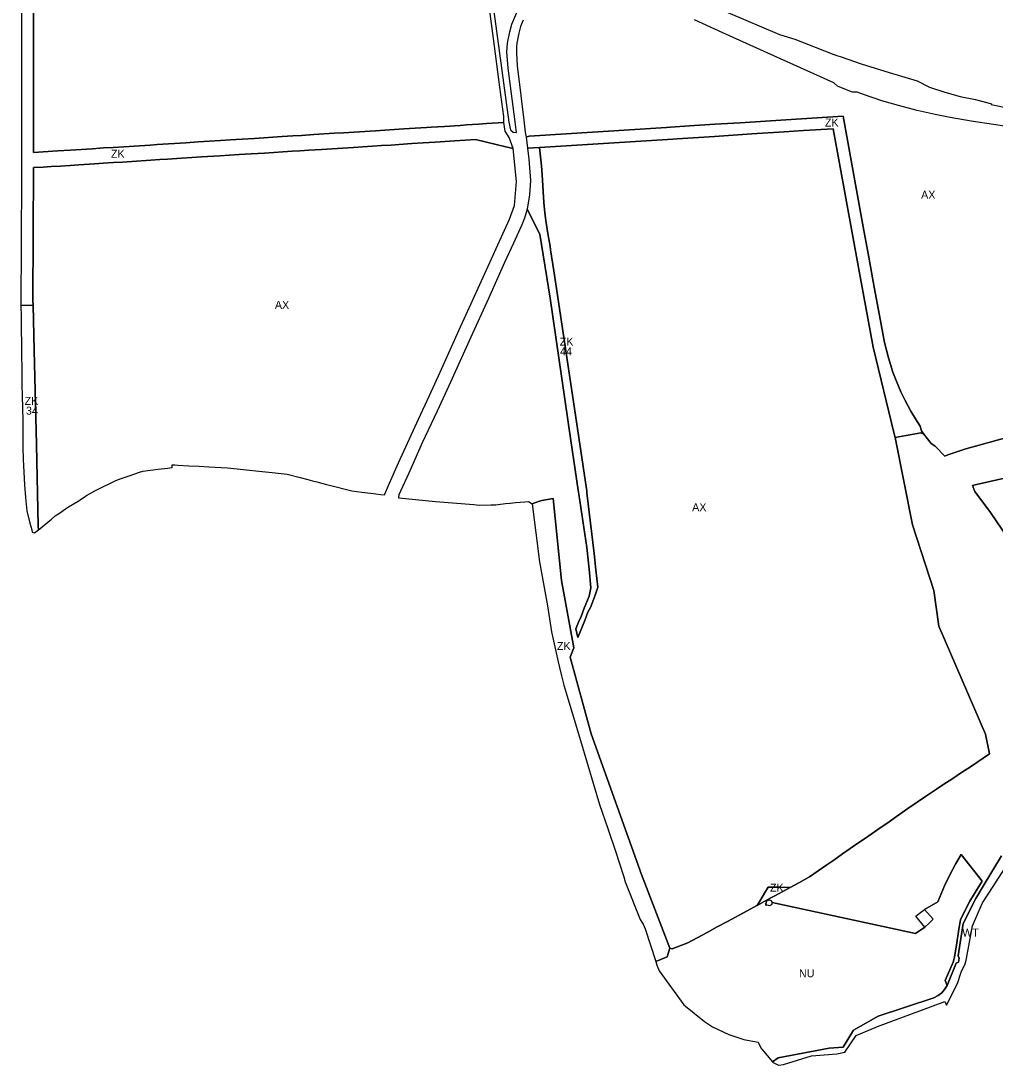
# Model space of a CAD drawing. Extents: x -521939 to -516426, y -1197857 to -1189551.
# Drawn here: x -520595 to -519377, y -1194163 to -1192859 of the extents above; entities that cross this region are included whole.
import ezdxf

# ---------------------------------------------------------------- set-up
doc = ezdxf.new("R2010")
doc.units = 0
for name, color, linetype in [('90640013', 7, 'Continuous'), ('90710013', 7, 'Continuous'), ('90710023', 7, 'Continuous'), ('90730013', 7, 'Continuous'), ('90760013', 7, 'Continuous'), ('ID_navrh', 7, 'Continuous')]:
    doc.layers.add(name, color=color, linetype=linetype)

msp = doc.modelspace()

# ---------------------------------------------------------------- linework, layer by layer
at = {"layer": '90640013'}
msp.add_lwpolyline([(-519369.32, -1193902.04), (-519392.44, -1193939.94), (-519401.67, -1193955.07), (-519417.38, -1193986.45), (-519423.71, -1194026.84), (-519422.25, -1194029.85), (-519423.14, -1194034.81), (-519426.12, -1194036.14), (-519437.56, -1194064.1), (-519440.57, -1194068.9), (-519444.16, -1194073.19), (-519448.49, -1194076.43), (-519453.99, -1194079.26), (-519523.58, -1194102.28), (-519554.3, -1194119.84), (-519567.25, -1194140.88), (-519584.65, -1194142.29), (-519648.63, -1194154.46), (-519655.75, -1194159.37), (-519655.45, -1194159.52), (-519647.94, -1194163.37), (-519641.85, -1194162.57), (-519606.91, -1194151.78), (-519575.26, -1194149.43), (-519565.1, -1194147.14), (-519550.87, -1194126.48), (-519524.59, -1194115.17), (-519440.38, -1194083.75), (-519438.01, -1194088.36), (-519424.43, -1194061.23), (-519420.05, -1194047.18), (-519414.79, -1194036.92), (-519413.61, -1194032.27), (-519413.11, -1194030.31), (-519405.75, -1193989.16), (-519399.04, -1193973.83), (-519393.3, -1193960.72), (-519380, -1193940.17), (-519361.83, -1193912.1)], dxfattribs=at)
at = {"layer": '90710013'}
for points in [[(-520593.65, -1192846.53), (-520593.65, -1192886.47), (-520593.65, -1192919.05), (-520593.65, -1192951.65), (-520593.65, -1193003.95), (-520593.65, -1193022.39), (-520593.65, -1193025.86), (-520593.83, -1193063.74), (-520594.11, -1193124.54), (-520594.19, -1193141.12), (-520594.27, -1193157.6), (-520594.44, -1193193.51), (-520594.51, -1193208.54), (-520594.54, -1193214.33), (-520579.39, -1193213.66), (-520579.51, -1193208.61), (-520578.73, -1193042.06), (-520566.88, -1193041.27), (-520556.71, -1193040.64), (-520545.11, -1193039.99), (-520533.1, -1193039.2), (-520522.29, -1193038.46), (-520502.67, -1193037.25), (-520491.62, -1193036.59), (-520478.81, -1193035.71), (-520467.56, -1193034.99), (-520455.8, -1193034.25), (-520432.23, -1193032.75), (-520420.8, -1193032.06), (-520411.37, -1193031.46), (-520393.95, -1193030.39), (-520380.96, -1193029.53), (-520368.83, -1193028.73), (-520345.83, -1193027.27), (-520322.05, -1193025.77), (-520306.84, -1193024.79), (-520290.21, -1193023.75), (-520255.59, -1193021.55), (-520245.93, -1193020.94), (-520240.07, -1193020.58), (-520234.93, -1193020.24), (-520219.13, -1193019.25), (-520178.86, -1193016.69), (-520167.73, -1193015.98), (-520155.48, -1193015.24), (-520143.99, -1193014.49), (-520132.24, -1193013.75), (-520106.15, -1193012.06), (-520091.82, -1193011.2), (-520077.11, -1193010.24), (-520052.32, -1193008.69), (-520026.61, -1193007.06), (-519988.7, -1193015.91), (-519979.35, -1193018.09), (-519984.44, -1193004.38), (-519989.51, -1192996.39), (-519991.05, -1192985.7), (-520012.89, -1192987.09), (-520022.91, -1192987.66), (-520037.92, -1192988.72), (-520045.66, -1192989.26), (-520065.26, -1192990.45), (-520082.11, -1192991.54), (-520087.74, -1192991.91), (-520116.16, -1192993.69), (-520151.57, -1192995.93), (-520178, -1192997.58), (-520191.65, -1192998.39), (-520203.14, -1192999.13), (-520228.56, -1193000.81), (-520243.85, -1193001.69), (-520254.89, -1193002.46), (-520268.06, -1193003.31), (-520302.87, -1193005.42), (-520317.98, -1193006.45), (-520333.21, -1193007.43), (-520345.29, -1193008.1), (-520358.83, -1193009.02), (-520373, -1193009.89), (-520388.44, -1193010.92), (-520424.27, -1193013.22), (-520433.04, -1193013.75), (-520479.44, -1193016.7), (-520491.25, -1193017.47), (-520505.08, -1193018.37), (-520533.01, -1193020.12), (-520548.56, -1193021.06), (-520578.65, -1193022.99), (-520578.65, -1192845.72)], [(-519961.59, -1193017.82), (-519946.52, -1193016.85), (-519780.28, -1193006.26), (-519774.46, -1193005.9), (-519728.13, -1193002.94), (-519693.03, -1193000.71), (-519681.4, -1192999.94), (-519640.92, -1192997.38), (-519616.64, -1192995.84), (-519579.74, -1192993.48), (-519548.08, -1193166.93), (-519529.92, -1193266.42), (-519503.38, -1193374.77), (-519502.33, -1193379.15), (-519470.46, -1193373.47), (-519466.38, -1193375.11), (-519469.48, -1193370.72), (-519471.11, -1193364.85), (-519476.92, -1193356.09), (-519482.58, -1193346.45), (-519490.34, -1193332.09), (-519495.18, -1193322.01), (-519501.24, -1193308), (-519505.08, -1193297.39), (-519510.86, -1193279.84), (-519515.74, -1193260.34), (-519522, -1193226.57), (-519528.39, -1193191.55), (-519535.25, -1193153.85), (-519542.14, -1193116.18), (-519550.99, -1193067.69), (-519567.38, -1192977.66), (-519638.79, -1192982.16), (-519695.85, -1192985.85), (-519727.53, -1192987.89), (-519759.2, -1192989.89), (-519777.13, -1192991.04), (-519783.15, -1192991.42), (-519787.9, -1192991.72), (-519959.5, -1193002.65), (-519963.23, -1193004.02), (-519961.59, -1193017.82)], [(-519783.96, -1194017.34), (-519819.1, -1193925.23), (-519882.21, -1193749.64), (-519908.38, -1193653.77), (-519903.71, -1193641.87), (-519919.19, -1193557.82), (-519929.74, -1193455.31), (-519943.76, -1193457.81), (-519947.7, -1193459.17), (-519955.63, -1193461.89), (-519946.78, -1193534.59), (-519936.7, -1193589.63), (-519931.56, -1193622.07), (-519923.3, -1193659.68), (-519921.57, -1193666.61), (-519919.01, -1193676.86), (-519916.08, -1193688.59), (-519895.34, -1193757.93), (-519871.53, -1193837.56), (-519861.11, -1193867.84), (-519850.99, -1193898.71), (-519847.64, -1193908.92), (-519841.31, -1193928.23), (-519839.55, -1193934.52), (-519820.78, -1193981.48), (-519818.64, -1193984.6), (-519816.99, -1193987.28), (-519814.49, -1193992.92), (-519801.37, -1194033.88), (-519786.98, -1194028.03), (-519783.96, -1194017.34)], [(-519674.87, -1193963.79), (-519665.13, -1193958.51), (-519661.44, -1193956.51), (-519657.74, -1193954.5), (-519652.7, -1193951.75), (-519633.36, -1193941.29), (-519647.22, -1193941.11), (-519661.09, -1193940.94), (-519665.71, -1193948.61), (-519670.34, -1193956.28), (-519674.87, -1193963.79)]]:
    msp.add_lwpolyline(points, dxfattribs=at)
at = {"layer": '90710023'}
for points in [[(-519962.06, -1193093.75), (-519946.35, -1193125.19), (-519933.38, -1193205.21), (-519907.35, -1193382.83), (-519898.22, -1193445.13), (-519897.8, -1193447.56), (-519897.38, -1193449.99), (-519887.36, -1193516.57), (-519884.47, -1193543.82), (-519882.69, -1193567.19), (-519884.76, -1193577.59), (-519890.7, -1193592.62), (-519894.55, -1193602.68), (-519897.73, -1193609.81), (-519901.37, -1193618.32), (-519898.76, -1193628.94), (-519889.94, -1193607.87), (-519886.16, -1193597.43), (-519883.14, -1193591.58), (-519880.89, -1193586.23), (-519877.16, -1193576.19), (-519873.92, -1193566.11), (-519876.28, -1193544.38), (-519878.23, -1193524.18), (-519887.53, -1193448.24), (-519887.69, -1193445.77), (-519887.86, -1193443.3), (-519901.66, -1193351.49), (-519928.77, -1193171.13), (-519932.83, -1193144.89), (-519933.44, -1193140.29), (-519936.08, -1193124.31), (-519938.56, -1193107.97), (-519940.04, -1193098.62), (-519941.21, -1193085.76), (-519943.25, -1193050.97), (-519944.11, -1193039.95), (-519945.63, -1193024.86), (-519946.52, -1193016.85), (-519961.59, -1193017.82), (-519959.95, -1193031.63), (-519957.98, -1193057.97), (-519959.22, -1193075.94), (-519962.06, -1193093.75)], [(-520572.69, -1193494.62), (-520572.81, -1193489.53), (-520575.23, -1193388.1), (-520578.05, -1193270.09), (-520579.39, -1193213.66), (-520594.54, -1193214.33), (-520594.36, -1193228.5), (-520594.2, -1193241.7), (-520593.91, -1193264.71), (-520593.84, -1193270.47), (-520593.48, -1193299.21), (-520593.16, -1193312.67), (-520592.81, -1193327.52), (-520592.34, -1193342.18), (-520592.11, -1193358.68), (-520592.07, -1193374.76), (-520592.13, -1193390.79), (-520591.63, -1193406.88), (-520590.94, -1193422.65), (-520590.74, -1193422.65), (-520589.86, -1193438.24), (-520588.57, -1193454.26), (-520586.93, -1193470.68), (-520583.19, -1193486.29), (-520581, -1193494.61), (-520580.28, -1193497.37), (-520577.34, -1193498.47), (-520572.69, -1193494.62)]]:
    msp.add_lwpolyline(points, dxfattribs=at)
at = {"layer": '90730013'}
for points in [[(-519363, -1193379.33), (-519414.21, -1193393.4), (-519436.58, -1193400.77), (-519440.32, -1193402.59), (-519452.18, -1193390.07), (-519457.37, -1193386.9), (-519466.38, -1193375.11), (-519470.46, -1193373.47), (-519502.33, -1193379.15), (-519480.86, -1193488.16), (-519453.95, -1193570.4), (-519447.84, -1193614.85), (-519389.47, -1193750.04), (-519384.42, -1193774.3), (-519408.2, -1193790.66), (-519418.05, -1193797.11), (-519431.74, -1193806.08), (-519441.36, -1193812.44), (-519450.66, -1193818.5), (-519464.32, -1193827.57), (-519486.62, -1193842.93), (-519503.63, -1193854.82), (-519509.92, -1193859.26), (-519524.03, -1193869.16), (-519536.51, -1193877.89), (-519553.25, -1193889.05), (-519568.04, -1193899.4), (-519579.1, -1193907.2), (-519587.75, -1193913.3), (-519609.4, -1193928.24), (-519622.78, -1193935.57), (-519633.36, -1193941.29), (-519652.7, -1193951.75), (-519657.74, -1193954.5), (-519661.44, -1193956.51), (-519659.93, -1193956.89), (-519657.33, -1193957.77), (-519656.64, -1193959), (-519655.91, -1193960.31), (-519477.05, -1193998.98), (-519465.18, -1193990.9)], [(-519355.68, -1193513.49), (-519383.3, -1193472.91), (-519402.88, -1193446.79), (-519405.79, -1193439.04), (-519400.65, -1193437.87), (-519323.14, -1193420.3)], [(-519674.87, -1193963.79), (-519675.09, -1193963.91), (-519687.29, -1193970.52), (-519711.79, -1193983.75), (-519724.57, -1193990.65), (-519737.33, -1193997.55), (-519761.2, -1194010.43), (-519780.88, -1194018.05), (-519783.96, -1194017.34), (-519786.98, -1194028.03), (-519801.37, -1194033.88), (-519799.88, -1194038.54), (-519797.27, -1194045.4), (-519766.42, -1194087.98), (-519740.5, -1194108.83), (-519730.5, -1194115.53), (-519710.16, -1194125.22), (-519691.18, -1194131.21), (-519673.57, -1194134.61), (-519672.17, -1194137.42), (-519669.38, -1194143.02), (-519668.94, -1194143.55), (-519655.75, -1194159.37), (-519648.63, -1194154.46), (-519584.65, -1194142.29), (-519567.25, -1194140.88), (-519554.3, -1194119.84), (-519523.58, -1194102.28), (-519453.99, -1194079.26), (-519448.49, -1194076.43), (-519444.16, -1194073.19), (-519440.57, -1194068.9), (-519437.56, -1194064.1), (-519439.91, -1194057.85), (-519429.83, -1194034.63), (-519428.59, -1194030.27), (-519428.22, -1194027.94), (-519425.91, -1194013.45), (-519422.59, -1193993.31), (-519420.77, -1193981.9), (-519415.68, -1193971.51), (-519408.84, -1193958.58), (-519404.57, -1193950.95), (-519401.16, -1193945.56), (-519393.46, -1193933.48), (-519419.72, -1193900.08), (-519426.85, -1193912.47), (-519433.98, -1193925.44), (-519440.59, -1193939.19), (-519448.9, -1193959.21), (-519465.49, -1193968.92), (-519454.84, -1193980.91), (-519460.01, -1193985.91), (-519465.18, -1193990.9), (-519477.05, -1193998.98), (-519655.91, -1193960.31), (-519656.75, -1193962.97), (-519659.4, -1193964.35), (-519662.02, -1193963.62), (-519662.24, -1193963.25), (-519663.26, -1193963.82), (-519663.79, -1193962.87), (-519664.31, -1193961.92), (-519663.23, -1193961.31), (-519663.44, -1193960.89), (-519662.65, -1193958.29), (-519659.93, -1193956.89), (-519661.44, -1193956.51), (-519665.13, -1193958.51), (-519674.87, -1193963.79)], [(-519465.18, -1193990.9), (-519476.58, -1193977.08), (-519472.45, -1193974.05), (-519465.49, -1193968.92), (-519448.9, -1193959.21), (-519440.59, -1193939.19), (-519433.98, -1193925.44), (-519426.85, -1193912.47), (-519419.72, -1193900.08), (-519393.46, -1193933.48), (-519401.16, -1193945.56), (-519404.57, -1193950.95), (-519408.84, -1193958.58), (-519415.68, -1193971.51), (-519420.77, -1193981.9), (-519422.59, -1193993.31), (-519425.91, -1194013.45), (-519428.22, -1194027.94), (-519428.59, -1194030.27), (-519429.83, -1194034.63), (-519439.91, -1194057.85), (-519437.56, -1194064.1), (-519426.12, -1194036.14), (-519423.14, -1194034.81), (-519422.25, -1194029.85), (-519423.71, -1194026.84), (-519417.38, -1193986.45), (-519401.67, -1193955.07), (-519392.44, -1193939.94), (-519369.32, -1193902.04)]]:
    msp.add_lwpolyline(points, dxfattribs=at)
at = {"layer": '90760013'}
for points in [[(-520578.65, -1192845.72), (-520578.65, -1193022.99), (-520548.56, -1193021.06), (-520533.01, -1193020.12), (-520505.08, -1193018.37), (-520491.25, -1193017.47), (-520479.44, -1193016.7), (-520433.04, -1193013.75), (-520424.27, -1193013.22), (-520388.44, -1193010.92), (-520373, -1193009.89), (-520358.83, -1193009.02), (-520345.29, -1193008.1), (-520333.21, -1193007.43), (-520317.98, -1193006.45), (-520302.87, -1193005.42), (-520268.06, -1193003.31), (-520254.89, -1193002.46), (-520243.85, -1193001.69), (-520228.56, -1193000.81), (-520203.14, -1192999.13), (-520191.65, -1192998.39), (-520178, -1192997.58), (-520151.57, -1192995.93), (-520116.16, -1192993.69), (-520087.74, -1192991.91), (-520082.11, -1192991.54), (-520065.26, -1192990.45), (-520045.66, -1192989.26), (-520037.92, -1192988.72), (-520022.91, -1192987.66), (-520012.89, -1192987.09), (-519991.05, -1192985.7), (-519991.11, -1192978.26), (-519996.02, -1192941.34), (-520004.11, -1192880.48), (-520009.13, -1192843.07)], [(-520003.51, -1192847.12), (-519985.11, -1192985.35), (-519982.68, -1192994.68), (-519979.39, -1192997.86), (-519975.28, -1192998.31)], [(-519975.28, -1192998.31), (-519976.99, -1192984.86), (-519985.67, -1192917.82), (-519987.63, -1192897.15), (-519986.6, -1192886.41), (-519983.86, -1192872.26), (-519981.06, -1192862.78), (-519973.79, -1192845.48)], [(-519711.44, -1192848.38), (-519646.77, -1192875.82), (-519627.56, -1192881.34), (-519578.96, -1192900.47), (-519578.65, -1192900.59), (-519575.19, -1192901.81), (-519569.95, -1192903.63), (-519544.98, -1192912.28), (-519509.74, -1192923.15), (-519475.01, -1192933.77), (-519459.24, -1192941.4), (-519440.39, -1192947.55), (-519421.33, -1192953.08), (-519401.78, -1192957), (-519382, -1192962.28), (-519382.21, -1192963.28), (-519360.04, -1192967.68)], [(-519966.94, -1192857.93), (-519970.35, -1192865.66), (-519972.67, -1192873.95), (-519975.08, -1192886.33), (-519975.27, -1192891.17), (-519975.59, -1192898.9), (-519974.75, -1192915.01), (-519972.14, -1192935.43), (-519970.58, -1192948.05), (-519968.79, -1192962.75), (-519968.01, -1192968.78), (-519966.28, -1192982.61), (-519964.4, -1192997.62), (-519963.23, -1193004.02), (-519959.5, -1193002.65), (-519787.9, -1192991.72), (-519783.15, -1192991.42), (-519777.13, -1192991.04), (-519759.2, -1192989.89), (-519727.53, -1192987.89), (-519695.85, -1192985.85), (-519638.79, -1192982.16), (-519567.38, -1192977.66), (-519550.99, -1193067.69), (-519542.14, -1193116.18), (-519535.25, -1193153.85), (-519528.39, -1193191.55), (-519522, -1193226.57), (-519515.74, -1193260.34), (-519510.86, -1193279.84), (-519505.08, -1193297.39), (-519501.24, -1193308), (-519495.18, -1193322.01), (-519490.34, -1193332.09), (-519482.58, -1193346.45), (-519476.92, -1193356.09), (-519471.11, -1193364.85), (-519469.48, -1193370.72), (-519466.38, -1193375.11), (-519457.37, -1193386.9), (-519452.18, -1193390.07), (-519440.32, -1193402.59), (-519436.58, -1193400.77), (-519414.21, -1193393.4), (-519363, -1193379.33)], [(-519316.79, -1192997.86), (-519379.4, -1192988.21), (-519407.22, -1192983.93), (-519433.72, -1192979.51), (-519452.37, -1192975.76), (-519474.87, -1192970.68), (-519498.2, -1192964.55), (-519518.93, -1192958.37), (-519542.07, -1192950.61), (-519549.76, -1192947.78), (-519555.74, -1192947.57), (-519567.2, -1192943.06), (-519574.51, -1192940.18), (-519579.08, -1192936.23), (-519653.99, -1192902.46), (-519717.76, -1192873.41), (-519752.94, -1192857.37)], [(-519674.87, -1193963.79), (-519670.34, -1193956.28), (-519665.71, -1193948.61), (-519661.09, -1193940.94), (-519647.22, -1193941.11), (-519633.36, -1193941.29), (-519622.78, -1193935.57), (-519609.4, -1193928.24), (-519587.75, -1193913.3), (-519579.1, -1193907.2), (-519568.04, -1193899.4), (-519553.25, -1193889.05), (-519536.51, -1193877.89), (-519524.03, -1193869.16), (-519509.92, -1193859.26), (-519503.63, -1193854.82), (-519486.62, -1193842.93), (-519464.32, -1193827.57), (-519450.66, -1193818.5), (-519441.36, -1193812.44), (-519431.74, -1193806.08), (-519418.05, -1193797.11), (-519408.2, -1193790.66), (-519384.42, -1193774.3), (-519389.47, -1193750.04), (-519447.84, -1193614.85), (-519453.95, -1193570.4), (-519480.86, -1193488.16), (-519502.33, -1193379.15), (-519503.38, -1193374.77), (-519529.92, -1193266.42), (-519548.08, -1193166.93), (-519579.74, -1192993.48), (-519616.64, -1192995.84), (-519640.92, -1192997.38), (-519681.4, -1192999.94), (-519693.03, -1193000.71), (-519728.13, -1193002.94), (-519774.46, -1193005.9), (-519780.28, -1193006.26), (-519946.52, -1193016.85), (-519945.63, -1193024.86), (-519944.11, -1193039.95), (-519943.25, -1193050.97), (-519941.21, -1193085.76), (-519940.04, -1193098.62), (-519938.56, -1193107.97), (-519936.08, -1193124.31), (-519933.44, -1193140.29), (-519932.83, -1193144.89), (-519928.77, -1193171.13), (-519901.66, -1193351.49), (-519887.86, -1193443.3), (-519887.69, -1193445.77), (-519887.53, -1193448.24), (-519878.23, -1193524.18), (-519876.28, -1193544.38), (-519873.92, -1193566.11), (-519877.16, -1193576.19), (-519880.89, -1193586.23), (-519883.14, -1193591.58), (-519886.16, -1193597.43), (-519889.94, -1193607.87), (-519898.76, -1193628.94), (-519901.37, -1193618.32), (-519897.73, -1193609.81), (-519894.55, -1193602.68), (-519890.7, -1193592.62), (-519884.76, -1193577.59), (-519882.69, -1193567.19), (-519884.47, -1193543.82), (-519887.36, -1193516.57), (-519897.38, -1193449.99), (-519897.8, -1193447.56), (-519898.22, -1193445.13), (-519907.35, -1193382.83), (-519933.38, -1193205.21), (-519946.35, -1193125.19), (-519962.06, -1193093.75), (-519965.3, -1193105.27), (-519968.9, -1193113.5), (-519979.15, -1193136.45), (-519990.26, -1193160.72), (-520002.08, -1193186.73), (-520010.57, -1193205.51), (-520032.44, -1193253.64), (-520057.96, -1193310.06), (-520074.37, -1193346.48), (-520093.16, -1193385.99), (-520110.08, -1193423.75), (-520120.13, -1193446.45), (-520122.19, -1193450.64), (-520122.83, -1193454.58), (-520118.08, -1193455.09), (-520076.7, -1193459.13), (-520028.77, -1193463.02), (-520025.22, -1193463.32), (-520021.66, -1193463.62), (-520007.58, -1193463.4), (-520001.4, -1193463.3), (-519998.48, -1193462.95), (-519989.19, -1193461.84), (-519983.09, -1193461.11), (-519976.68, -1193460.34), (-519964.98, -1193459.47), (-519960.33, -1193459.13), (-519955.63, -1193461.89), (-519947.7, -1193459.17), (-519943.76, -1193457.81), (-519929.74, -1193455.31), (-519919.19, -1193557.82), (-519903.71, -1193641.87), (-519908.38, -1193653.77), (-519882.21, -1193749.64), (-519819.1, -1193925.23), (-519783.96, -1194017.34), (-519780.88, -1194018.05), (-519761.2, -1194010.43), (-519737.33, -1193997.55), (-519724.57, -1193990.65), (-519711.79, -1193983.75), (-519687.29, -1193970.52), (-519675.09, -1193963.91), (-519674.87, -1193963.79)], [(-519979.35, -1193018.09), (-519988.7, -1193015.91), (-520026.61, -1193007.06), (-520052.32, -1193008.69), (-520077.11, -1193010.24), (-520091.82, -1193011.2), (-520106.15, -1193012.06), (-520132.24, -1193013.75), (-520143.99, -1193014.49), (-520155.48, -1193015.24), (-520167.73, -1193015.98), (-520178.86, -1193016.69), (-520219.13, -1193019.25), (-520234.93, -1193020.24), (-520240.07, -1193020.58), (-520245.93, -1193020.94), (-520255.59, -1193021.55), (-520290.21, -1193023.75), (-520306.84, -1193024.79), (-520322.05, -1193025.77), (-520345.83, -1193027.27), (-520368.83, -1193028.73), (-520380.96, -1193029.53), (-520393.95, -1193030.39), (-520411.37, -1193031.46), (-520420.8, -1193032.06), (-520432.23, -1193032.75), (-520455.8, -1193034.25), (-520467.56, -1193034.99), (-520478.81, -1193035.71), (-520491.62, -1193036.59), (-520502.67, -1193037.25), (-520522.29, -1193038.46), (-520533.1, -1193039.2), (-520545.11, -1193039.99), (-520556.71, -1193040.64), (-520566.88, -1193041.27), (-520578.73, -1193042.06), (-520579.51, -1193208.61), (-520579.39, -1193213.66), (-520578.05, -1193270.09), (-520575.23, -1193388.1), (-520572.81, -1193489.53), (-520572.69, -1193494.62), (-520556.47, -1193481.19), (-520552.19, -1193477.64), (-520551.51, -1193477.08), (-520546.33, -1193473.58), (-520538.63, -1193468.36), (-520534.87, -1193466.02), (-520523.12, -1193458.7), (-520520.53, -1193457.08), (-520515.1, -1193453.26), (-520512.4, -1193451.62), (-520508.9, -1193449.5), (-520502.06, -1193445.99), (-520494.81, -1193442.28), (-520493.13, -1193441.44), (-520481.96, -1193435.8), (-520476.06, -1193432.83), (-520469.36, -1193430.53), (-520458.12, -1193426.67), (-520446.45, -1193422.65), (-520442, -1193421.12), (-520422.98, -1193418.9), (-520411.57, -1193417.55), (-520405.38, -1193416.83), (-520405.38, -1193413.23), (-520402.17, -1193413.42), (-520398.39, -1193413.64), (-520384.74, -1193414.44), (-520371.74, -1193415.2), (-520359.55, -1193415.91), (-520336.49, -1193417.25), (-520332.09, -1193417.51), (-520312.6, -1193419.64), (-520297.31, -1193421.3), (-520280.67, -1193423.11), (-520261.82, -1193425.17), (-520245.85, -1193429.27), (-520235.96, -1193431.81), (-520230.21, -1193433.29), (-520225.01, -1193434.63), (-520212.61, -1193437.82), (-520209.03, -1193438.74), (-520181.19, -1193445.89), (-520168.44, -1193447.43), (-520157.33, -1193448.78), (-520145.02, -1193450.27), (-520140.41, -1193450.83), (-520133.9, -1193436.21), (-520122.68, -1193410.82), (-520097.84, -1193356.45), (-520084.24, -1193326.9), (-520070.77, -1193297.42), (-520047.22, -1193245.62), (-520021.04, -1193188.07), (-519984.32, -1193106.32), (-519978.09, -1193089.18), (-519975.45, -1193059.33), (-519979.35, -1193018.09)], [(-519323.14, -1193420.3), (-519400.65, -1193437.87), (-519405.79, -1193439.04), (-519402.88, -1193446.79), (-519383.3, -1193472.91), (-519355.68, -1193513.49)]]:
    msp.add_lwpolyline(points, dxfattribs=at)

# ---------------------------------------------------------------- texts
at = {"layer": '90640013'}
msp.add_text('WT', height=10, rotation=0, dxfattribs=at).set_placement((-519418.48, -1194002.7))
at = {"layer": '90710013'}
for rotation, p in [(360, (-519590.1, -1192990.64)), (360, (-520482.02, -1193029.72)), (0, (-519924.87, -1193644.73)), (360, (-519658.73, -1193946.68))]:
    msp.add_text('ZK', height=10, rotation=rotation, dxfattribs=at).set_placement(p)
at = {"layer": '90710023'}
for rotation, p in [(360, (-519921.33, -1193264.44)), (0, (-520589.92, -1193338.47))]:
    msp.add_text('ZK', height=10, rotation=rotation, dxfattribs=at).set_placement(p)
at = {"layer": '90730013'}
msp.add_text('NU', height=10, rotation=360, dxfattribs=at).set_placement((-519622.5, -1194053.6))
at = {"layer": '90760013'}
for rotation, p in [(360, (-519469.9, -1193080.87)), (360, (-520277.19, -1193218.57)), (0, (-519755.93, -1193471.32))]:
    msp.add_text('AX', height=10, rotation=rotation, dxfattribs=at).set_placement(p)
at = {"layer": 'ID_navrh'}
for s, p in [('44', (-519921, -1193276.66)), ('34', (-520588.2, -1193350.7))]:
    msp.add_text(s, height=10, rotation=360, dxfattribs=at).set_placement(p)

doc.saveas('drawing.dxf')
